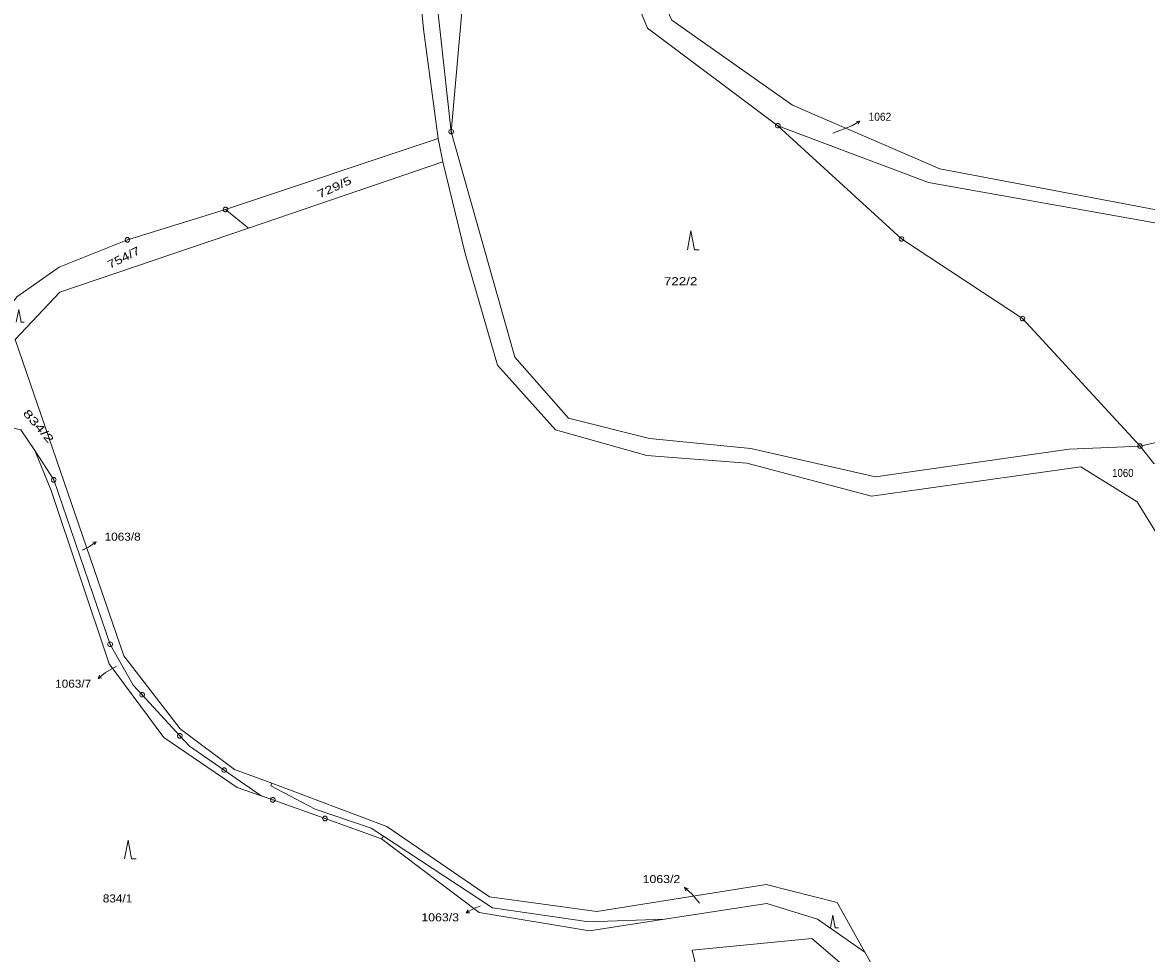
# Model space of a CAD drawing. Extents: x -687390 to -684106, y -954833 to -951648.
# Drawn here: x -686980 to -686741.2, y -953758.4 to -953560.6 of the extents above; entities that cross this region are included whole.
import ezdxf
from ezdxf.enums import TextEntityAlignment as Align

# ---------------------------------------------------------------- set-up
doc = ezdxf.new("R2010")
doc.units = 0
doc.header["$LTSCALE"] = 0.68
for name, color, linetype, lineweight in [('1', 7, 'Continuous', 13), ('3', 7, 'Continuous', 13), ('7', 7, 'Continuous', 13), ('8', 7, 'Continuous', 13)]:
    doc.layers.add(name, color=color, linetype=linetype, lineweight=lineweight)
doc.layers.add('2', color=7, linetype='Continuous')

msp = doc.modelspace()

# ---------------------------------------------------------------- linework, layer by layer
at = {"layer": '1'}
for p, q in [((-686894.86, -953562.01), (-686891.72, -953585.25)), ((-686891.72, -953585.25), (-686936.89, -953600.31)), ((-686891.72, -953585.25), (-686890.73, -953590.2)), ((-686931.99, -953604.26), (-686890.73, -953590.2)), ((-686890.73, -953590.2), (-686885.99, -953609.64)), ((-686936.89, -953600.31), (-686957.74, -953606.77)), ((-686931.99, -953604.26), (-686936.89, -953600.31)), ((-686972.07, -953617.91), (-686931.99, -953604.26)), ((-686957.74, -953606.77), (-686972.27, -953612.53)), ((-686879.15, -953633.36), (-686885.99, -953609.64)), ((-686972.07, -953617.91), (-686981.59, -953627.91)), ((-686981.59, -953627.91), (-686958.5, -953695.18)), ((-686742.63, -953650.6), (-686757.67, -953651.21)), ((-686977.42, -953651.49), (-686973.41, -953657.77)), ((-686977.42, -953651.49), (-686973.93, -953660.05)), ((-686961.64, -953696.86), (-686973.93, -953660.05)), ((-686956.49, -953701.37), (-686954.62, -953703.43)), ((-686946.6, -953712.16), (-686954.62, -953703.43)), ((-686944.56, -953714.36), (-686946.6, -953712.16)), ((-686944.56, -953714.36), (-686937.19, -953719.45)), ((-686929.35, -953724.88), (-686937.19, -953719.45)), ((-686927.3, -953722.78), (-686927.09, -953722.25)), ((-686929.35, -953724.88), (-686934.43, -953723.16)), ((-686929.35, -953724.88), (-686926.85, -953725.77)), ((-686926.85, -953725.77), (-686915.77, -953729.73)), ((-686903.76, -953734.03), (-686915.77, -953729.73)), ((-686903.76, -953734.03), (-686903.36, -953733.47)), ((-686882.99, -953749.7), (-686903.76, -953734.03)), ((-686859.71, -953751.66), (-686880.18, -953748.73)), ((-686811.15, -953751.15), (-686821.94, -953747.77)), ((-686859.59, -953753.62), (-686882.99, -953749.7)), ((-686859.71, -953751.66), (-686843.67, -953751.15)), ((-686811.15, -953751.15), (-686801.06, -953758.1))]:
    msp.add_line(p, q, dxfattribs=at)
for points in [[(-687037.88, -953375.05), (-687023.89, -953388.57), (-687013.39, -953396.86), (-686991.55, -953427.26), (-686972.13, -953443.92), (-686960.08, -953450.71), (-686939.95, -953457.51), (-686924.36, -953467.19), (-686912.54, -953478.09), (-686903.13, -953503.34), (-686894.42, -953534.14), (-686888.97, -953583.77)], [(-687030.33, -953387.15), (-687019.11, -953395.83), (-686995.77, -953426.94), (-686974.61, -953447.17), (-686958.03, -953454.71), (-686941.83, -953460.86), (-686926.64, -953470), (-686915.85, -953479.55), (-686904.42, -953510.15), (-686897.13, -953538.3), (-686894.86, -953562.01)], [(-686848.55, -953472.7), (-686883.62, -953487.73), (-686882.83, -953502.66), (-686888.19, -953508.36), (-686886.1, -953551.96), (-686888.97, -953583.77)], [(-686844.24, -953487.5), (-686854.12, -953513.48), (-686856.02, -953540.32), (-686847.26, -953561.75), (-686819.56, -953582.52), (-686787.55, -953594.55), (-686737.1, -953603.57), (-686706.26, -953623.07), (-686659.76, -953633.42), (-686631.23, -953646.66)], [(-686839.79, -953489.19), (-686849.5, -953511.8), (-686851.99, -953538.73), (-686842.1, -953560.06), (-686816.44, -953578.15), (-686785.17, -953591.65), (-686735.45, -953601.12), (-686703.86, -953620.79), (-686657.58, -953631.09), (-686629.18, -953645.02), (-686610.63, -953664.49), (-686593.4, -953691.27), (-686585.18, -953724.8), (-686575.37, -953740.35), (-686548.41, -953769.8), (-686529.04, -953794.51)], [(-686888.97, -953583.77), (-686875.42, -953631.69), (-686864.05, -953644.66), (-686846.8, -953648.95), (-686825.3, -953651.12), (-686798.82, -953657.12), (-686757.67, -953651.21)], [(-686819.56, -953582.52), (-686793.3, -953606.57), (-686767.59, -953623.5), (-686742.63, -953650.6)], [(-686983.6, -953622.05), (-686981.22, -953618.89), (-686972.27, -953612.53)], [(-686879.15, -953633.36), (-686866.82, -953647.12), (-686847.43, -953652.56), (-686826.16, -953654.24), (-686799.69, -953661.22), (-686755.17, -953654.97), (-686743.22, -953662.45), (-686732.82, -953679.38)], [(-686742.63, -953650.6), (-686723.81, -953646.27), (-686687.41, -953652.88), (-686657.22, -953644.56), (-686643.5, -953644.07), (-686628.42, -953651.54)], [(-686977.42, -953651.49), (-686980.39, -953647.15), (-686987.83, -953645.51)], [(-686742.63, -953650.6), (-686739.68, -953654.27), (-686723.08, -953649.73)], [(-686956.49, -953701.37), (-686961.39, -953692.72), (-686973.41, -953657.77)], [(-686934.97, -953719.29), (-686946.55, -953710.69), (-686958.5, -953695.18)], [(-686934.43, -953723.16), (-686950, -953712.5), (-686961.64, -953696.86)], [(-686902.61, -953731.46), (-686927.09, -953722.25), (-686934.97, -953719.29)], [(-686905.97, -953731.75), (-686917.84, -953727.74), (-686927.3, -953722.78)], [(-686880.18, -953748.73), (-686903.36, -953733.47), (-686905.97, -953731.75)], [(-686806.97, -953747.57), (-686822.07, -953743.74), (-686858.04, -953749.5), (-686880.79, -953746.4), (-686902.61, -953731.46)], [(-686821.94, -953747.77), (-686843.67, -953751.15), (-686859.59, -953753.62)], [(-686799.5, -953760.89), (-686801.06, -953758.1), (-686806.97, -953747.57)], [(-686797.12, -953808.02), (-686803.52, -953762.79), (-686812.34, -953755.19), (-686837.76, -953757.7)], [(-686837.76, -953757.7), (-686836.27, -953763.87), (-686906.67, -953773.47), (-686950.39, -953788.8)]]:
    msp.add_lwpolyline(points, dxfattribs=at)
at = {"layer": '3'}
for points in [[(-686838.79, -953608.87), (-686838.04, -953604.87), (-686837.29, -953608.87), (-686836.29, -953608.87)], [(-686981.342, -953624.26), (-686980.84, -953621.58), (-686980.338, -953624.26), (-686979.668, -953624.26)], [(-686958.35, -953738.33), (-686957.6, -953734.33), (-686956.85, -953738.33), (-686955.85, -953738.33)], [(-686808.362, -953752.93), (-686807.86, -953750.25), (-686807.358, -953752.93), (-686806.688, -953752.93)]]:
    msp.add_lwpolyline(points, dxfattribs=at)
at = {"layer": '7'}
for p, q in [((-686802.118, -953581.544), (-686803.87, -953582.53)), ((-686807.9, -953584.1), (-686803.87, -953582.53)), ((-686967.34, -953672.72), (-686966.04, -953672.06)), ((-686964.398, -953670.901), (-686966.04, -953672.06)), ((-686963.956, -953699.967), (-686962.38, -953698.72)), ((-686960.05, -953697.37), (-686962.38, -953698.72)), ((-686839.375, -953744.387), (-686837.87, -953745.72)), ((-686836.19, -953747.71), (-686837.87, -953745.72)), ((-686885.783, -953749.773), (-686884.03, -953748.79)), ((-686882.81, -953748.32), (-686884.03, -953748.79))]:
    msp.add_line(p, q, dxfattribs=at)
for points in [[(-686802.867, -953581.581), (-686802.118, -953581.544), (-686802.538, -953582.165)], [(-686965.138, -953671.014), (-686964.398, -953670.901), (-686964.752, -953671.561)], [(-686963.223, -953699.814), (-686963.956, -953699.967), (-686963.639, -953699.289)], [(-686839.095, -953745.082), (-686839.375, -953744.387), (-686838.651, -953744.581)], [(-686885.035, -953749.738), (-686885.783, -953749.773), (-686885.363, -953749.153)]]:
    msp.add_lwpolyline(points, dxfattribs=at)
at = {"layer": '8'}
for p, q in [((-686889.09, -953583.77), (-686888.85, -953583.77)), ((-686819.68, -953582.52), (-686819.44, -953582.52)), ((-686937.01, -953600.31), (-686936.77, -953600.31)), ((-686957.86, -953606.77), (-686957.62, -953606.77)), ((-686793.42, -953606.57), (-686793.18, -953606.57)), ((-686767.71, -953623.5), (-686767.47, -953623.5)), ((-686742.75, -953650.6), (-686742.51, -953650.6)), ((-686973.53, -953657.77), (-686973.29, -953657.77)), ((-686961.51, -953692.72), (-686961.27, -953692.72)), ((-686954.74, -953703.43), (-686954.5, -953703.43)), ((-686946.72, -953712.16), (-686946.48, -953712.16)), ((-686937.31, -953719.45), (-686937.07, -953719.45)), ((-686926.97, -953725.77), (-686926.73, -953725.77)), ((-686915.89, -953729.73), (-686915.65, -953729.73))]:
    msp.add_line(p, q, dxfattribs=at)
for points in [[(-686819.41, -953582.04), (-686819.16, -953582.22), (-686819.06, -953582.51), (-686819.16, -953582.8), (-686819.41, -953582.98), (-686819.72, -953582.98), (-686819.97, -953582.8), (-686820.07, -953582.51), (-686819.97, -953582.22), (-686819.72, -953582.04)], [(-686888.82, -953583.29), (-686888.57, -953583.47), (-686888.47, -953583.76), (-686888.57, -953584.05), (-686888.82, -953584.23), (-686889.13, -953584.23), (-686889.38, -953584.05), (-686889.48, -953583.76), (-686889.38, -953583.47), (-686889.13, -953583.29)], [(-686936.74, -953599.83), (-686936.49, -953600.01), (-686936.39, -953600.3), (-686936.49, -953600.59), (-686936.74, -953600.77), (-686937.05, -953600.77), (-686937.3, -953600.59), (-686937.4, -953600.3), (-686937.3, -953600.01), (-686937.05, -953599.83)], [(-686957.59, -953606.29), (-686957.34, -953606.47), (-686957.24, -953606.76), (-686957.34, -953607.05), (-686957.59, -953607.23), (-686957.9, -953607.23), (-686958.15, -953607.05), (-686958.25, -953606.76), (-686958.15, -953606.47), (-686957.9, -953606.29)], [(-686793.15, -953606.09), (-686792.9, -953606.27), (-686792.8, -953606.56), (-686792.9, -953606.85), (-686793.15, -953607.03), (-686793.46, -953607.03), (-686793.71, -953606.85), (-686793.81, -953606.56), (-686793.71, -953606.27), (-686793.46, -953606.09)], [(-686767.44, -953623.02), (-686767.19, -953623.2), (-686767.09, -953623.49), (-686767.19, -953623.78), (-686767.44, -953623.96), (-686767.75, -953623.96), (-686768, -953623.78), (-686768.1, -953623.49), (-686768, -953623.2), (-686767.75, -953623.02)], [(-686742.48, -953650.12), (-686742.23, -953650.3), (-686742.13, -953650.59), (-686742.23, -953650.88), (-686742.48, -953651.06), (-686742.79, -953651.06), (-686743.04, -953650.88), (-686743.14, -953650.59), (-686743.04, -953650.3), (-686742.79, -953650.12)], [(-686973.26, -953657.29), (-686973.01, -953657.47), (-686972.91, -953657.76), (-686973.01, -953658.05), (-686973.26, -953658.23), (-686973.57, -953658.23), (-686973.82, -953658.05), (-686973.92, -953657.76), (-686973.82, -953657.47), (-686973.57, -953657.29)], [(-686961.24, -953692.24), (-686960.99, -953692.42), (-686960.89, -953692.71), (-686960.99, -953693), (-686961.24, -953693.18), (-686961.55, -953693.18), (-686961.8, -953693), (-686961.9, -953692.71), (-686961.8, -953692.42), (-686961.55, -953692.24)], [(-686954.47, -953702.95), (-686954.22, -953703.13), (-686954.12, -953703.42), (-686954.22, -953703.71), (-686954.47, -953703.89), (-686954.78, -953703.89), (-686955.03, -953703.71), (-686955.13, -953703.42), (-686955.03, -953703.13), (-686954.78, -953702.95)], [(-686946.45, -953711.68), (-686946.2, -953711.86), (-686946.1, -953712.15), (-686946.2, -953712.44), (-686946.45, -953712.62), (-686946.76, -953712.62), (-686947.01, -953712.44), (-686947.11, -953712.15), (-686947.01, -953711.86), (-686946.76, -953711.68)], [(-686937.04, -953718.97), (-686936.79, -953719.15), (-686936.69, -953719.44), (-686936.79, -953719.73), (-686937.04, -953719.91), (-686937.35, -953719.91), (-686937.6, -953719.73), (-686937.7, -953719.44), (-686937.6, -953719.15), (-686937.35, -953718.97)], [(-686926.7, -953725.29), (-686926.45, -953725.47), (-686926.35, -953725.76), (-686926.45, -953726.05), (-686926.7, -953726.23), (-686927.01, -953726.23), (-686927.26, -953726.05), (-686927.36, -953725.76), (-686927.26, -953725.47), (-686927.01, -953725.29)], [(-686915.62, -953729.25), (-686915.37, -953729.43), (-686915.27, -953729.72), (-686915.37, -953730.01), (-686915.62, -953730.19), (-686915.93, -953730.19), (-686916.18, -953730.01), (-686916.28, -953729.72), (-686916.18, -953729.43), (-686915.93, -953729.25)]]:
    msp.add_lwpolyline(points, close=True, dxfattribs=at)

# ---------------------------------------------------------------- texts
at = {"layer": '2'}
for s, height, width, p in [('1062', 0.1, 0.95, (-686807.854, -953584.1)), ('722/2', 1.7, 1.25, (-686843.775, -953616.39)), ('1060', 1.7, 0.9, (-686748.555, -953657.14)), ('1063/8', 0.1, 1.1, (-686967.294, -953672.72)), ('1063/7', 0.1, 1.1, (-686960.004, -953697.37)), ('834/1', 1.7, 1.1, (-686962.975, -953747.56)), ('1063/3', 0.1, 1.15, (-686882.764, -953748.32)), ('1063/2', 0.1, 1.15, (-686836.144, -953747.71))]:
    msp.add_text(s, height=height, dxfattribs=dict(at, width=width)).set_placement(p)
for s, rotation, width, p in [('729/5', 24.924, 1.35, (-686916.899, -953597.96)), ('754/7', 26.757, 1.3, (-686961.476, -953612.946))]:
    msp.add_text(s, height=1.7, rotation=rotation, dxfattribs=dict(at, width=width)).set_placement(p)
at = {"layer": '7'}
for s, width, p in [('1062', 0.95, (-686800.285, -953581.45)), ('1063/8', 1.1, (-686962.585, -953670.69))]:
    msp.add_text(s, height=1.7, dxfattribs=dict(at, width=width)).set_placement(p)
at = {"layer": '7', "width": 1.5}
msp.add_text('834/2', height=1.7, rotation=310.715, dxfattribs=at).set_placement((-686980.059, -953643.679))
at = {"layer": '7'}
for s, width, p in [('1063/7', 1.1, (-686965.446, -953701.93)), ('1063/2', 1.15, (-686840.296, -953743.44)), ('1063/3', 1.15, (-686887.306, -953751.58))]:
    msp.add_text(s, height=1.7, dxfattribs=dict(at, width=width)).set_placement(p, align=Align.RIGHT)

doc.saveas('drawing.dxf')
